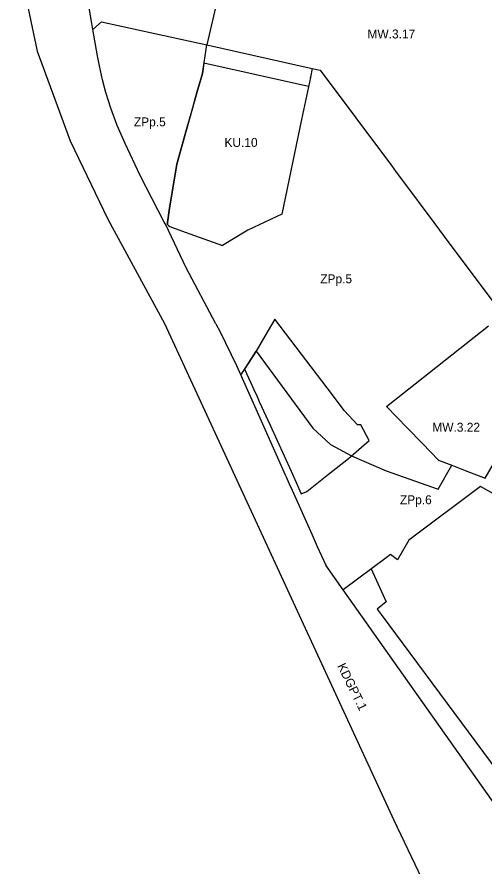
# Model space of a CAD drawing. Extents: x 7428239 to 7429836, y 5549133 to 5550853.
# Drawn here: x 7428331.5 to 7428593.3, y 5549408.8 to 5549884.9 of the extents above; entities that cross this region are included whole.
import ezdxf

# ---------------------------------------------------------------- set-up
doc = ezdxf.new("R2010")
doc.units = 0
for name, color, linetype in [('LIN_linie rozgraniczające', 7, 'Continuous'), ('LIN_nieprzekraczalna linia zabudowy', 7, 'Continuous'), ('TXT_Oznaczenia Przeznaczenia', 7, 'Continuous')]:
    doc.layers.add(name, color=color, linetype=linetype)

msp = doc.modelspace()

# ---------------------------------------------------------------- linework, layer by layer
at = {"layer": 'LIN_linie rozgraniczające'}
for p, q in [((7428453.98, 5549937.74), (7428437.91, 5549869.27)), ((7428331.47, 5549919.94), (7428342.74, 5549865.69)), ((7428378.82, 5549882.18), (7428374.01, 5549878)), ((7428435.41, 5549853.31), (7428437.91, 5549869.27)), ((7428437.91, 5549869.27), (7428497.06, 5549856.11)), ((7428497.06, 5549856.11), (7428496.04, 5549851.21)), ((7428497.06, 5549856.11), (7428501.45, 5549855.14)), ((7428501.45, 5549855.14), (7428541.4, 5549801.61)), ((7428496.01, 5549851.07), (7428491.08, 5549827.45)), ((7428496.01, 5549851.07), (7428496.04, 5549851.21)), ((7428491.08, 5549827.45), (7428479.99, 5549774.28)), ((7428541.4, 5549801.61), (7428544.09, 5549797.99)), ((7428544.09, 5549797.99), (7428547.15, 5549793.9)), ((7428547.15, 5549793.9), (7428565.21, 5549769.69)), ((7428479.99, 5549774.28), (7428460.88, 5549765.31)), ((7428382.35, 5549771.51), (7428414.21, 5549713.07)), ((7428565.21, 5549769.69), (7428574.24, 5549757.58)), ((7428423.75, 5549765.08), (7428430.91, 5549762.49)), ((7428460.88, 5549765.31), (7428446.78, 5549756.74)), ((7428430.91, 5549762.49), (7428446.78, 5549756.74)), ((7428574.24, 5549757.58), (7428583.39, 5549745.32)), ((7428583.39, 5549745.32), (7428601.61, 5549720.87)), ((7428414.21, 5549713.07), (7428542.7, 5549434.61)), ((7428442.98, 5549712.88), (7428445.44, 5549708.3)), ((7428538.72, 5549666.5), (7428595.85, 5549711.72)), ((7428445.44, 5549708.3), (7428454.56, 5549689.48)), ((7428456.97, 5549684.05), (7428465.54, 5549697.57)), ((7428465.54, 5549697.57), (7428497.29, 5549654.38)), ((7428454.56, 5549689.48), (7428456.97, 5549684.05)), ((7428456.97, 5549684.05), (7428468.32, 5549658.47)), ((7428468.32, 5549658.47), (7428481.88, 5549628.2)), ((7428497.29, 5549654.38), (7428507.18, 5549645.12)), ((7428507.18, 5549645.12), (7428519.07, 5549638.78)), ((7428481.88, 5549628.2), (7428482.41, 5549627.01)), ((7428482.41, 5549627.01), (7428484.12, 5549623.22)), ((7428484.12, 5549623.22), (7428485.73, 5549619.58)), ((7428604.31, 5549614.44), (7428591.41, 5549621.67)), ((7428485.73, 5549619.58), (7428495.99, 5549596.69)), ((7428495.99, 5549596.69), (7428496.94, 5549594.54)), ((7428496.94, 5549594.54), (7428499.84, 5549588.08)), ((7428499.84, 5549588.08), (7428504.54, 5549577.61)), ((7428540.9, 5549583.46), (7428538.45, 5549581.63)), ((7428538.45, 5549581.63), (7428514.4, 5549563.66)), ((7428514.4, 5549563.66), (7428504.54, 5549577.61)), ((7428542.7, 5549434.61), (7428648.42, 5549212.88))]:
    msp.add_line(p, q, dxfattribs=at)
for points in [[(7428442.98, 5549712.88), (7428426.27, 5549744.28), (7428414.66, 5549768.71), (7428414.07, 5549769.9), (7428400.61, 5549796.12), (7428392.11, 5549813.98), (7428387.72, 5549824.14), (7428384.1, 5549833.89), (7428381.38, 5549842.53), (7428379.45, 5549849.69), (7428377.68, 5549857.51), (7428376.6, 5549863.19), (7428374.01, 5549878), (7428373.45, 5549881.19), (7428364.82, 5549932.56), (7428363.45, 5549944.39), (7428363.2, 5549946.59), (7428362.02, 5549961.25), (7428361.31, 5549978.67)], [(7428378.82, 5549882.18), (7428389.17, 5549879.92), (7428402.84, 5549876.93), (7428437.91, 5549869.27)], [(7428342.74, 5549865.69), (7428361.33, 5549815.4), (7428382.35, 5549771.51)], [(7428417.07, 5549777.79), (7428421.03, 5549802.33), (7428426.53, 5549821.9), (7428429.43, 5549832.16), (7428432.53, 5549843.08), (7428435.02, 5549851.91), (7428435.41, 5549853.31)], [(7428415.91, 5549768.64), (7428415.8, 5549769.71), (7428417.07, 5549777.79)], [(7428415.91, 5549768.64), (7428416.35, 5549767.98), (7428417.08, 5549767.49), (7428423.75, 5549765.08)], [(7428538.72, 5549666.5), (7428550.23, 5549654.63), (7428558.81, 5549645.78), (7428567.86, 5549636.45), (7428575.32, 5549633.58), (7428582.79, 5549630.71), (7428594, 5549626.4), (7428611.26, 5549656.29)], [(7428519.07, 5549638.78), (7428538.53, 5549630.35), (7428567.58, 5549620.14), (7428575.32, 5549633.58)], [(7428591.41, 5549621.67), (7428551.16, 5549591.63), (7428544.82, 5549580.62), (7428540.9, 5549583.46)], [(7428692.12, 5549505.06), (7428664.86, 5549484.98), (7428621.96, 5549453.36), (7428622.78, 5549451.92), (7428624.33, 5549449.21), (7428626.78, 5549444.02), (7428619.09, 5549439.74), (7428615.65, 5549446.03), (7428614.73, 5549447.7), (7428602.83, 5549438.62), (7428514.4, 5549563.66)]]:
    msp.add_lwpolyline(points, dxfattribs=at)
at = {"layer": 'LIN_nieprzekraczalna linia zabudowy'}
for points in [[(7428494.94, 5549845.96), (7428436.3, 5549859.01), (7428435.41, 5549853.31), (7428432.53, 5549843.08), (7428426.53, 5549821.9), (7428421.03, 5549802.33), (7428417.07, 5549777.79), (7428415.8, 5549769.71), (7428415.91, 5549768.64), (7428416.35, 5549767.98), (7428417.08, 5549767.49), (7428423.75, 5549765.08), (7428430.91, 5549762.49), (7428446.78, 5549756.74)], [(7428473.49, 5549656.06), (7428485.13, 5549630.19), (7428490.84, 5549617.51), (7428493.97, 5549618.92), (7428506.21, 5549628.5), (7428517.4, 5549637.27), (7428528.96, 5549647.48), (7428524.24, 5549656.2), (7428522.33, 5549656.2), (7428517.3, 5549661.71), (7428514.98, 5549664.25), (7428508.28, 5549673.07), (7428476.1, 5549715.44), (7428470.48, 5549705.93), (7428465.54, 5549697.57), (7428459.09, 5549687.39)], [(7428459.09, 5549687.39), (7428462.42, 5549680.19), (7428464.09, 5549676.42), (7428466.05, 5549672.12), (7428467.32, 5549669.35), (7428473.49, 5549656.06)], [(7428530.12, 5549575.4), (7428538.48, 5549556.89)], [(7428538.48, 5549556.89), (7428533.38, 5549552.9), (7428535.68, 5549549.86), (7428600.98, 5549461.67), (7428612.81, 5549446.24)]]:
    msp.add_lwpolyline(points, dxfattribs=at)

# ---------------------------------------------------------------- texts
at = {"layer": 'TXT_Oznaczenia Przeznaczenia'}
for s, p in [('MW.3.17', (7428527.99, 5549872.89)), ('ZPp.5', (7428397.03, 5549823.61)), ('KU.10', (7428447.8, 5549812.09)), ('ZPp.5', (7428501.51, 5549735.59)), ('MW.3.22', (7428564.34, 5549652.38)), ('ZPp.6', (7428546.18, 5549611.7))]:
    msp.add_text(s, height=5, dxfattribs=at).set_placement(p)
msp.add_text('KDGPT.1', height=5, rotation=296.3089, dxfattribs=at).set_placement((7428510.9, 5549521.05))

doc.saveas('drawing.dxf')
